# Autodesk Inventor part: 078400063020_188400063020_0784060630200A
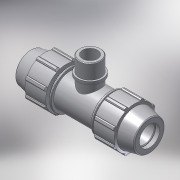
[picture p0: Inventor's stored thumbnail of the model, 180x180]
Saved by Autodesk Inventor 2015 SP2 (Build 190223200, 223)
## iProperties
Created: 2017-02
Part Number: 078400063020_188400063020_0784060630200A
Material: PVC-Piping
Description: PLASSON TEE WITH THREADED MALE OFFTAKE 63-2"-63
Document SubType Name: Modeling
Designer: KIM
Mass: 92.6774 g
Surface Area: 199.44 cm^2
Volume: 66.1981 cm^3
Density: 1.4 g/cm^3
Appearance: Smooth - White
Author: Кирилл
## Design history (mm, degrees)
derived "07840.ipt"
feature "Solid1::07840.ipt"
feature "Solid2::07840.ipt"
tag "TaggingFeature1"
body "Solid1"
body "Solid2"
other parameters: "d2" = 63, "d4" = 11.33333, "d5" = 32.64, "d7" = 113, "d11" = 4.53333, "d13" = 120 deg, "d14" = 94.5, "d15" = 12 deg, "d16" = 98.31, "d18" = 3.15, "d19" = 35 deg, "d20" = 17.5 deg, "d21" = 105.09, "d23" = 0, "d25" = 360 deg, "d27" = 2.26, "d33" = 1.26, "d42" = 48.96, "d43" = 3.39, "d46" = 1.89, "d68" = 4.53333, "d72" = 92, "d73" = 59.614, "d74" = 26, "d75" = 68.5561, "d76" = 41.7298, "d77" = 31.2, "d80" = 1.78842, "d91" = 84.75, "d95" = 56.7, "d99" = 272, "d101" = 0, "d103" = 0, "d105" = 0, "d_" = 63, "E_" = 113, "A_" = 92, "l_2" = 26, "H_" = 272, "R_" = 59.614
